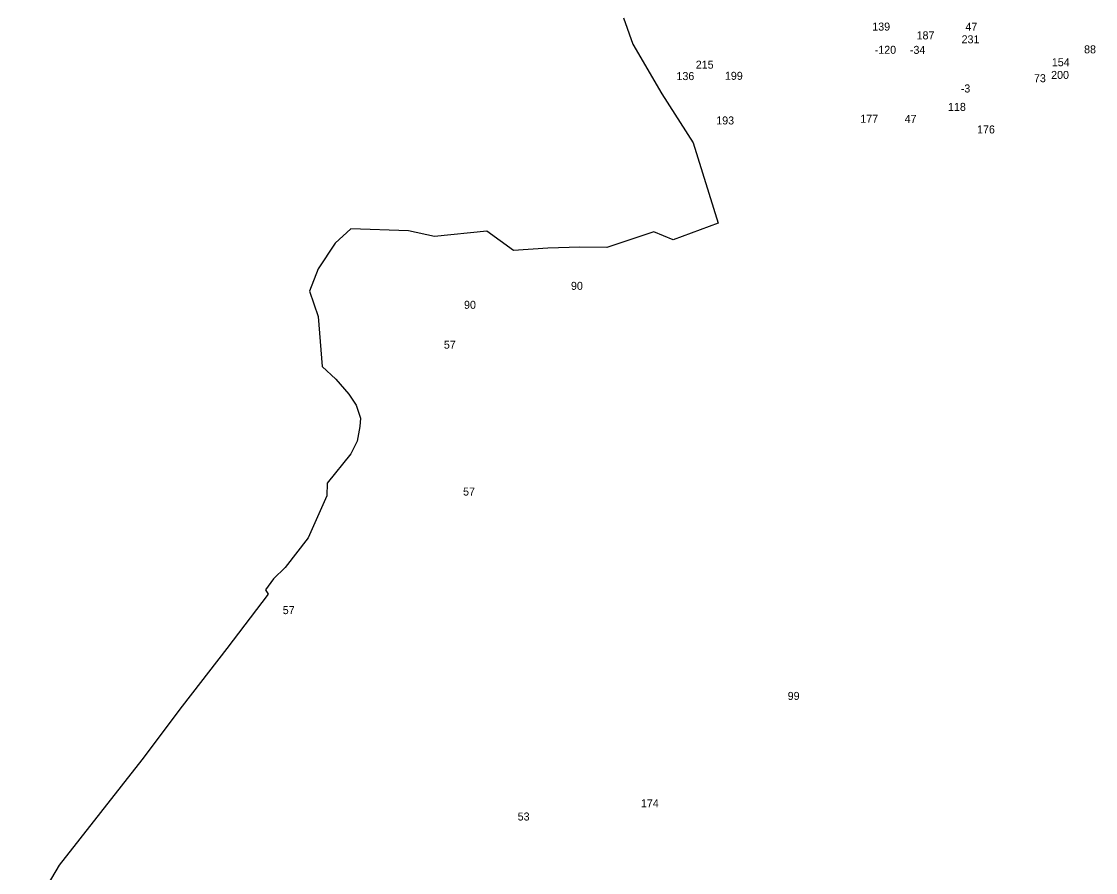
# Model space of a CAD drawing. Extents: x -783032 to -781233, y -975453 to -972360.
# Drawn here: x -782813 to -782040, y -973909 to -973296 of the extents above; entities that cross this region are included whole.
import ezdxf

# ---------------------------------------------------------------- set-up
doc = ezdxf.new("R2010")
doc.units = 0
doc.layers.add('Vrstva 13', color=7, linetype='Continuous')
doc.layers.add('Vrstva 24', color=7, linetype='Continuous')

msp = doc.modelspace()

# ---------------------------------------------------------------- linework, layer by layer
at = {"layer": 'Vrstva 13'}
for p, q in [((-782379.89, -973293.35), (-782373.16, -973312.3)), ((-782373.16, -973312.3), (-782352.25, -973348.16)), ((-782352.25, -973348.16), (-782329.58, -973383.53)), ((-782329.58, -973383.53), (-782311.72, -973441.42)), ((-782311.72, -973441.42), (-782344.07, -973453.25)), ((-782575.99, -973445.47), (-782587.33, -973455.62)), ((-782534.64, -973446.78), (-782575.99, -973445.47)), ((-782515.9, -973450.82), (-782534.64, -973446.78)), ((-782478.07, -973447.07), (-782515.9, -973450.82)), ((-782459.08, -973460.91), (-782478.07, -973447.07)), ((-782358.05, -973447.66), (-782391.79, -973458.74)), ((-782344.07, -973453.25), (-782358.05, -973447.66)), ((-782587.33, -973455.62), (-782599.6, -973474.2)), ((-782434.34, -973459.36), (-782459.08, -973460.91)), ((-782411.15, -973458.64), (-782434.34, -973459.36)), ((-782391.79, -973458.74), (-782411.15, -973458.64)), ((-782599.6, -973474.2), (-782605.86, -973490.17)), ((-782605.86, -973490.17), (-782599.65, -973508.61)), ((-782599.65, -973508.61), (-782596.61, -973544.63)), ((-782596.61, -973544.63), (-782586.98, -973553.74)), ((-782586.98, -973553.74), (-782577.46, -973564.56)), ((-782577.46, -973564.56), (-782572.33, -973572.33)), ((-782572.33, -973572.33), (-782569.22, -973581.76)), ((-782569.22, -973581.76), (-782569.53, -973587.77)), ((-782569.53, -973587.77), (-782571.49, -973598.42)), ((-782571.49, -973598.42), (-782576.15, -973607.38)), ((-782576.15, -973607.38), (-782593.07, -973628.56)), ((-782593.07, -973628.56), (-782593.28, -973637.78)), ((-782593.28, -973637.78), (-782606.89, -973667.99)), ((-782606.89, -973667.99), (-782623.35, -973689.33)), ((-782623.35, -973689.33), (-782631.78, -973697.52)), ((-782631.78, -973697.52), (-782637.42, -973705.29)), ((-782637.42, -973705.29), (-782635.55, -973708.6)), ((-782635.55, -973708.6), (-782665.27, -973747.73)), ((-782665.27, -973747.73), (-782697.47, -973789.04)), ((-782697.47, -973789.04), (-782726.55, -973827.86)), ((-782726.55, -973827.86), (-782786.08, -973903.69)), ((-782786.08, -973903.69), (-782813.2, -973949.16))]:
    msp.add_line(p, q, dxfattribs=at)

# ---------------------------------------------------------------- texts
at = {"layer": 'Vrstva 24'}
for s, p in [('139', (-782200.679, -973302.632)), ('47', (-782133.641, -973302.762)), ('187', (-782168.767, -973308.972)), ('231', (-782136.385, -973311.782)), ('-120', (-782198.929, -973319.35)), ('-34', (-782173.595, -973319.4)), ('88', (-782048.183, -973319.022)), ('215', (-782327.745, -973330.052)), ('154', (-782071.411, -973328.282)), ('136', (-782341.659, -973338.272)), ('199', (-782306.763, -973338.082)), ('73', (-782084.275, -973339.802)), ('200', (-782071.906, -973337.452)), ('-3', (-782136.97, -973347.2)), ('118', (-782146.148, -973360.452)), ('193', (-782313.009, -973370.222)), ('177', (-782209.289, -973369.032)), ('47', (-782177.401, -973369.152)), ('176', (-782125.241, -973376.702)), ('90', (-782417.603, -973489.322)), ('90', (-782494.593, -973502.982)), ('57', (-782509.125, -973531.692)), ('57', (-782495.275, -973637.492)), ('57', (-782625.095, -973722.862)), ('99', (-782261.579, -973784.652)), ('174', (-782367.243, -973861.982)), ('53', (-782455.963, -973871.492))]:
    msp.add_text(s, height=5.76, dxfattribs=at).set_placement(p)

doc.saveas('drawing.dxf')
